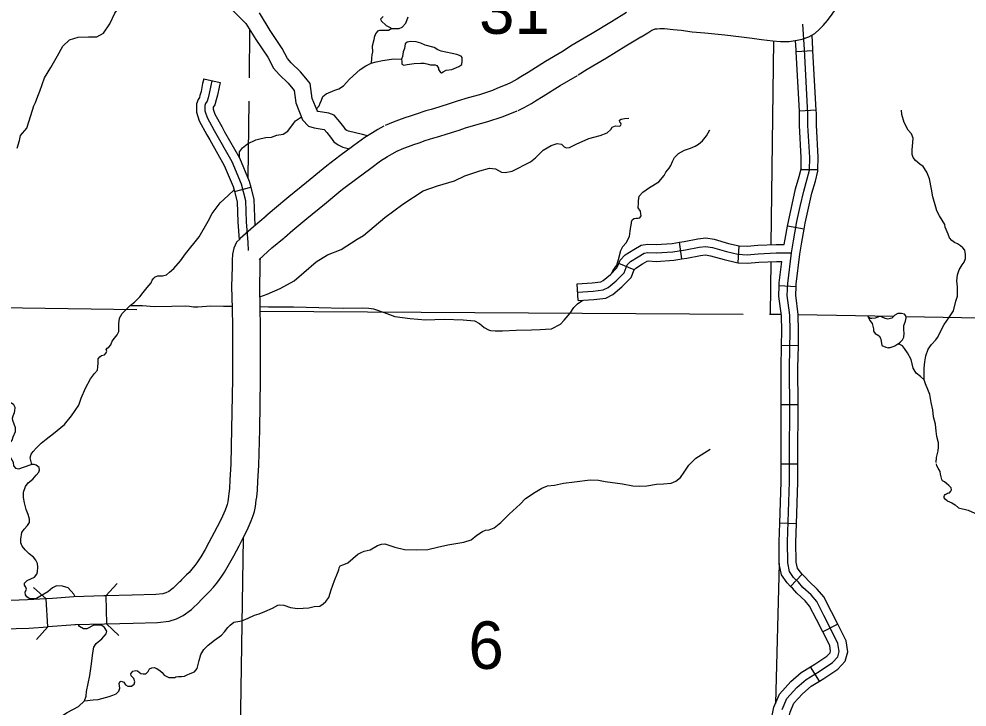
# Model space of a CAD drawing. Extents: x 813775 to 1157140, y 1757555 to 1979907.
# Drawn here: x 919245 to 936106, y 1805488 to 1817730 of the extents above; entities that cross this region are included whole.
import ezdxf

# ---------------------------------------------------------------- set-up
doc = ezdxf.new("R2010")
doc.units = 0
for name, color, linetype in [('Level 10', 7, 'Continuous'), ('Level 32', 7, 'Continuous'), ('Level 35', 7, 'Continuous'), ('Level 37', 7, 'Continuous'), ('Level 4', 7, 'Continuous'), ('Level 45', 7, 'Continuous'), ('Level 46', 7, 'Continuous'), ('Level 5', 7, 'Continuous')]:
    doc.layers.add(name, color=color, linetype=linetype)

msp = doc.modelspace()

# ---------------------------------------------------------------- linework, layer by layer
at = {"layer": 'Level 10'}
msp.add_line((919729, 1807412), (919728, 1807412), dxfattribs=at)
for points in [[(932941, 1817330), (933082, 1817351), (933176, 1817371), (933291, 1817410), (933399, 1817472), (933484, 1817548), (933549, 1817614), (933623, 1817700), (933708, 1817818), (933759, 1817895), (933804, 1817974), (933858, 1818084), (933893, 1818172), (933930, 1818273), (933950, 1818367), (933979, 1818481), (934011, 1818621), (934078, 1818907)], [(930052, 1817842), (929781, 1817681), (929436, 1817469), (929084, 1817263), (928913, 1817149)], [(932948, 1810031), (932952, 1810762), (932948, 1811526), (932961, 1812180), (932952, 1812461), (932908, 1812808), (932917, 1813026), (932984, 1813568), (933018, 1813784), (933081, 1814128), (933139, 1814395), (933201, 1814668), (933263, 1814886), (933303, 1815041), (933308, 1815268), (933277, 1815837), (933277, 1816041), (933214, 1817185), (933187, 1817639)], [(930309, 1817413), (930431, 1817486), (930500, 1817531), (930516, 1817539), (930559, 1817552), (930597, 1817557), (930641, 1817559), (930674, 1817559), (930726, 1817558), (930878, 1817542), (931020, 1817529), (931218, 1817503), (931444, 1817481), (931797, 1817447), (932093, 1817414), (932285, 1817389), (932451, 1817363), (932651, 1817339), (932786, 1817327), (932941, 1817330)], [(929190, 1816733), (929349, 1816839), (929693, 1817040), (930039, 1817253), (930307, 1817412)], [(928926, 1817158), (928608, 1816974), (928299, 1816778)], [(928301, 1816779), (928170, 1816698), (928106, 1816658), (928001, 1816601), (927907, 1816556)], [(928566, 1816355), (928867, 1816546), (929177, 1816725)], [(927921, 1816562), (927756, 1816496), (927664, 1816457), (927438, 1816382), (927234, 1816326), (927039, 1816270), (926914, 1816227), (926711, 1816162), (926574, 1816119), (926482, 1816095), (926310, 1816039), (926205, 1816003), (926105, 1815971), (925993, 1815929), (925900, 1815893), (925758, 1815833)], [(928121, 1816104), (928230, 1816155), (928358, 1816226), (928433, 1816273), (928565, 1816354)], [(925953, 1815373), (926087, 1815429), (926171, 1815461), (926270, 1815499), (926363, 1815529), (926468, 1815565), (926622, 1815614), (926714, 1815638), (926863, 1815686), (927071, 1815752), (927189, 1815793), (927369, 1815844), (927583, 1815903), (927840, 1815989), (927945, 1816033), (928107, 1816098)], [(925736, 1815822), (925626, 1815762), (925533, 1815704), (925397, 1815620), (925203, 1815477), (924953, 1815292), (924719, 1815118), (924654, 1815066), (924358, 1814823), (924043, 1814563), (923790, 1814350), (923638, 1814219)], [(923966, 1813841), (924114, 1813970), (924363, 1814179), (924676, 1814437), (924969, 1814677), (925025, 1814722), (925251, 1814891), (925501, 1815075), (925677, 1815205), (925798, 1815280), (925879, 1815331), (925975, 1815384)], [(923643, 1814223), (923413, 1814034), (923181, 1813822)], [(923178, 1813820), (923112, 1813757), (923068, 1813651), (923045, 1813547), (923037, 1813441), (923035, 1813322), (923027, 1812968), (923034, 1812576), (923041, 1812259), (923042, 1811776), (923040, 1811322), (923026, 1810437), (923011, 1809810), (922994, 1809530), (922987, 1809378), (922979, 1809290), (922971, 1809240), (922958, 1809138), (922948, 1809091), (922937, 1809054), (922912, 1808990), (922865, 1808884), (922827, 1808806), (922772, 1808694), (922718, 1808592), (922622, 1808413), (922558, 1808293), (922482, 1808159), (922443, 1808105), (922406, 1808052), (922370, 1808005), (922319, 1807944), (922269, 1807884), (922227, 1807842), (922135, 1807750), (922104, 1807718)], [(923518, 1813453), (923740, 1813656), (923961, 1813837)], [(922463, 1807370), (922491, 1807399), (922581, 1807489), (922638, 1807547), (922703, 1807623), (922762, 1807694), (922809, 1807757), (922850, 1807815), (922903, 1807889), (922996, 1808051), (923064, 1808178), (923159, 1808357), (923217, 1808465), (923277, 1808586), (923319, 1808674), (923374, 1808799), (923411, 1808894), (923432, 1808967), (923451, 1809054), (923465, 1809166), (923476, 1809224), (923486, 1809345), (923493, 1809504), (923511, 1809788), (923526, 1810427), (923540, 1811318), (923542, 1811776), (923540, 1812265), (923534, 1812586), (923527, 1812967), (923535, 1813313), (923536, 1813417), (923541, 1813472), (923542, 1813475)], [(932815, 1805442), (932899, 1805638), (933077, 1805833), (933246, 1805980), (933476, 1806123), (933712, 1806279), (933805, 1806381), (933832, 1806479), (933809, 1806621), (933721, 1806803), (933561, 1807114), (933432, 1807367), (933334, 1807483), (933188, 1807616), (933108, 1807710), (933019, 1807794), (932948, 1807901), (932917, 1808052), (932913, 1808425), (932948, 1809493), (932948, 1810031)], [(922108, 1807722), (921990, 1807605), (921910, 1807546), (921859, 1807522), (921804, 1807503), (921677, 1807489), (921261, 1807481), (920788, 1807466)], [(919728, 1807412), (919397, 1807393), (918947, 1807377), (918581, 1807360), (918462, 1807352), (918379, 1807350), (918272, 1807340), (918198, 1807326), (918090, 1807302), (917932, 1807258), (917819, 1807221), (917712, 1807173), (917572, 1807107), (917385, 1807018), (917163, 1806881), (916972, 1806779), (916557, 1806545), (916243, 1806375), (915913, 1806218), (915717, 1806116)], [(920220, 1807449), (919842, 1807419), (919728, 1807412)], [(919757, 1806913), (919729, 1807412)], [(920788, 1807466), (920754, 1807465), (920220, 1807449)], [(920788, 1807466), (920803, 1806966)], [(920803, 1806966), (921274, 1806981), (921710, 1806990), (921915, 1807013), (922047, 1807058), (922168, 1807115), (922316, 1807225), (922459, 1807366)], [(920803, 1806966), (920769, 1806965), (920241, 1806949)], [(915948, 1805672), (916136, 1805770), (916470, 1805929), (916799, 1806107), (917213, 1806340), (917413, 1806447), (917625, 1806578), (917786, 1806655), (917920, 1806718), (918000, 1806754), (918079, 1806780), (918212, 1806817), (918297, 1806836), (918340, 1806844), (918410, 1806850), (918487, 1806853), (918609, 1806861), (918967, 1806877), (919421, 1806893), (919757, 1806913)], [(920253, 1806950), (919757, 1806913)]]:
    msp.add_lwpolyline(points, dxfattribs=at)
at = {"layer": 'Level 32'}
for p, q in [((933366, 1817163), (933066, 1817147)), ((933423, 1816109), (933124, 1816092)), ((933453, 1815043), (933153, 1815048)), ((933209, 1813991), (932914, 1814045)), ((931033, 1813460), (930992, 1813757)), ((932037, 1813394), (932053, 1813693)), ((930188, 1813264), (929911, 1813380)), ((929189, 1812720), (929171, 1813020)), ((933065, 1812967), (932765, 1812979)), ((933106, 1811917), (932806, 1811923)), ((933102, 1810865), (932802, 1810863)), ((933098, 1809808), (932798, 1809808)), ((933073, 1808748), (932774, 1808758)), ((933175, 1807853), (932968, 1807635)), ((933808, 1806961), (933541, 1806824)), ((933481, 1805949), (933323, 1806204))]:
    msp.add_line(p, q, dxfattribs=at)
for points in [[(933366, 1817163), (933364, 1817193), (933349, 1817444)], [(933066, 1817147), (933065, 1817176), (933054, 1817347)], [(933124, 1816092), (933066, 1817147)], [(933423, 1816109), (933366, 1817163)], [(933153, 1815048), (933158, 1815265), (933127, 1815833), (933127, 1816037), (933124, 1816092)], [(933453, 1815043), (933458, 1815270), (933427, 1815841), (933427, 1816045), (933423, 1816109)], [(932914, 1814045), (932934, 1814157), (932993, 1814427), (933056, 1814705), (933118, 1814925), (933154, 1815062), (933153, 1815048)], [(933209, 1813991), (933228, 1814098), (933285, 1814362), (933346, 1814631), (933408, 1814846), (933453, 1815021), (933453, 1815043)], [(932856, 1813717), (932870, 1813810), (932914, 1814045)], [(933065, 1812967), (933067, 1813013), (933132, 1813547), (933166, 1813759), (933209, 1813991)], [(929911, 1813380), (929934, 1813436), (930024, 1813533), (930181, 1813629), (930310, 1813704), (930421, 1813726), (930576, 1813717), (930859, 1813738), (930992, 1813757)], [(930992, 1813757), (931072, 1813768), (931318, 1813817), (931459, 1813833), (931608, 1813811), (931863, 1813738), (932051, 1813693), (932053, 1813693)], [(932053, 1813693), (932195, 1813686), (932384, 1813703), (932710, 1813717), (932856, 1813717)], [(929180, 1812870), (929454, 1812887), (929636, 1812909), (929721, 1812953), (929867, 1813073), (930005, 1813215), (930063, 1813353), (930120, 1813415), (930258, 1813500), (930364, 1813562), (930431, 1813575), (930578, 1813567), (930875, 1813589), (931097, 1813620), (931341, 1813669), (931457, 1813682), (931577, 1813664), (931825, 1813593), (932029, 1813544), (932198, 1813535), (932393, 1813553), (932713, 1813567), (932984, 1813568)], [(929171, 1813020), (929441, 1813036), (929591, 1813054), (929637, 1813079), (929765, 1813184), (929877, 1813300), (929911, 1813380)], [(930188, 1813264), (930191, 1813271), (930216, 1813298), (930335, 1813371), (930418, 1813420), (930441, 1813425), (930579, 1813416), (930891, 1813440), (931033, 1813460)], [(931033, 1813460), (931122, 1813472), (931365, 1813520), (931454, 1813531), (931545, 1813517), (931787, 1813448), (932008, 1813395), (932037, 1813394)], [(932037, 1813394), (932201, 1813385), (932403, 1813404), (932717, 1813417), (932814, 1813417)], [(932765, 1812979), (932767, 1813038), (932814, 1813417)], [(929189, 1812720), (929468, 1812737), (929682, 1812763), (929804, 1812828), (929969, 1812963), (930132, 1813131), (930188, 1813264)], [(932806, 1811923), (932811, 1812179), (932803, 1812449), (932758, 1812801), (932765, 1812979)], [(933106, 1811917), (933111, 1812180), (933102, 1812473), (933058, 1812814), (933065, 1812967)], [(932802, 1810863), (932798, 1811527), (932806, 1811923)], [(933102, 1810865), (933098, 1811525), (933106, 1811917)], [(932798, 1809808), (932798, 1810031), (932802, 1810762), (932802, 1810863)], [(933098, 1809808), (933098, 1810030), (933102, 1810762), (933102, 1810865)], [(932774, 1808758), (932798, 1809496), (932798, 1809808)], [(933073, 1808748), (933098, 1809491), (933098, 1809808)], [(932968, 1807635), (932904, 1807697), (932807, 1807842), (932767, 1808036), (932763, 1808427), (932774, 1808758)], [(933175, 1807853), (933135, 1807891), (933089, 1807960), (933067, 1808068), (933063, 1808423), (933073, 1808748)], [(933808, 1806961), (933694, 1807182), (933558, 1807451), (933443, 1807587), (933296, 1807721), (933217, 1807813), (933175, 1807853)], [(933541, 1806824), (933427, 1807046), (933306, 1807284), (933226, 1807379), (933080, 1807512), (932999, 1807606), (932968, 1807635)], [(933323, 1806204), (933396, 1806249), (933613, 1806393), (933670, 1806455), (933678, 1806487), (933665, 1806575), (933586, 1806736), (933541, 1806824)], [(933481, 1805949), (933557, 1805997), (933810, 1806164), (933940, 1806306), (933985, 1806470), (933954, 1806666), (933855, 1806870), (933808, 1806961)], [(932633, 1805306), (932671, 1805488), (932771, 1805720), (932972, 1805941), (933156, 1806101), (933323, 1806204)], [(932926, 1805244), (932959, 1805397), (933027, 1805555), (933182, 1805726), (933335, 1805859), (933481, 1805949)]]:
    msp.add_lwpolyline(points, dxfattribs=at)
at = {"layer": 'Level 35'}
for points in [[(920630, 1817414), (920750, 1817480), (920861, 1817642), (920952, 1817834), (921053, 1817975), (921164, 1818278)], [(925722, 1817774), (925673, 1817728), (925693, 1817691)], [(925688, 1817694), (925773, 1817615), (925834, 1817583), (925876, 1817559), (925937, 1817561), (926006, 1817559), (926057, 1817583), (926123, 1817657), (926169, 1817769)], [(925876, 1817559), (925817, 1817522), (925734, 1817525), (925656, 1817525), (925619, 1817515), (925585, 1817464), (925563, 1817402), (925556, 1817358), (925526, 1817248), (925534, 1817148), (925519, 1817089), (925512, 1817033), (925508, 1816943)], [(919700, 1816680), (919813, 1816864), (919929, 1817074), (920025, 1817248), (920143, 1817356), (920300, 1817404), (920479, 1817409), (920630, 1817414)], [(926045, 1817016), (926051, 1816965), (926051, 1816924), (926090, 1816907), (926146, 1816919), (926271, 1816936), (926390, 1816943), (926449, 1816943), (926498, 1816934), (926562, 1816912), (926608, 1816912), (926647, 1816914), (926679, 1816902), (926706, 1816855), (926708, 1816833), (926728, 1816794), (926743, 1816775), (926760, 1816770), (926791, 1816789), (926843, 1816821), (926943, 1816828), (927065, 1816882), (927119, 1816921), (927129, 1816985), (927124, 1817044), (927109, 1817068), (927033, 1817098), (926752, 1817154), (926694, 1817181), (926630, 1817220), (926466, 1817264), (926390, 1817298), (926307, 1817323), (926207, 1817328), (926151, 1817318), (926112, 1817289), (926100, 1817205), (926078, 1817144), (926068, 1817063), (926045, 1817016)], [(924709, 1816400), (924865, 1816461), (924933, 1816488), (925019, 1816542), (925126, 1816657), (925315, 1816828), (925415, 1816897), (925508, 1816943), (925596, 1816968), (925711, 1816992), (925914, 1817019), (926045, 1817016)], [(919212, 1815429), (919254, 1815566), (919274, 1815657), (919387, 1815788), (919455, 1816011), (919511, 1816183), (919539, 1816246), (919581, 1816357), (919614, 1816448), (919700, 1816680)], [(924535, 1816129), (924584, 1816184), (924604, 1816231), (924626, 1816287), (924650, 1816348), (924709, 1816400)], [(935060, 1815754), (934985, 1815889), (934947, 1816033), (934940, 1816106)], [(923164, 1815259), (923168, 1815364), (923222, 1815438), (923310, 1815511), (923459, 1815580), (923550, 1815604), (923633, 1815619), (923736, 1815624), (923831, 1815661), (923944, 1815683), (924024, 1815736), (924127, 1815869), (924164, 1815920), (924269, 1815986)], [(925370, 1813878), (925749, 1814195), (926070, 1814434), (926436, 1814674), (926688, 1814760), (926991, 1814848), (927172, 1814938), (927443, 1815028), (927614, 1815075), (927722, 1815062), (927827, 1815004), (927890, 1815001), (928015, 1815021), (928340, 1815190), (928433, 1815258), (928568, 1815395), (928707, 1815481), (928817, 1815515), (928893, 1815503), (928939, 1815454), (928976, 1815437), (929035, 1815444), (929157, 1815500), (929377, 1815606), (929582, 1815659), (929704, 1815703), (929768, 1815766), (929797, 1815805), (929853, 1815827), (929929, 1815823), (929946, 1815842), (929956, 1815857), (929948, 1815874), (929929, 1815893), (929926, 1815928), (929953, 1815950), (930012, 1815957), (930090, 1815967)], [(931080, 1815395), (931187, 1815431), (931268, 1815465), (931329, 1815504), (931400, 1815560), (931471, 1815649), (931532, 1815759)], [(935549, 1814381), (935499, 1814563), (935474, 1814700), (935436, 1814884), (935388, 1815002), (935325, 1815103), (935267, 1815149), (935191, 1815212), (935149, 1815265), (935128, 1815318), (935131, 1815401), (935144, 1815532), (935146, 1815608), (935118, 1815686), (935060, 1815754)], [(930300, 1814310), (930258, 1814367), (930260, 1814453), (930260, 1814497), (930273, 1814575), (930339, 1814649), (930459, 1814730), (930627, 1814832), (930720, 1814943), (930747, 1815004), (930806, 1815077), (930835, 1815124), (930866, 1815191), (930904, 1815263), (930977, 1815337), (931080, 1815395)], [(922682, 1814270), (922826, 1814461), (922963, 1814590), (923070, 1814690)], [(922448, 1813853), (922609, 1814130), (922682, 1814270)], [(929781, 1813197), (929806, 1813246), (929875, 1813351), (929909, 1813451), (929946, 1813608), (929982, 1813679), (930043, 1813747), (930105, 1813860), (930114, 1813955), (930129, 1814039), (930136, 1814090), (930139, 1814119), (930158, 1814161), (930188, 1814180), (930219, 1814185), (930256, 1814185), (930285, 1814193), (930312, 1814227), (930307, 1814264), (930300, 1814310)], [(936066, 1813618), (936028, 1813659), (935988, 1813695), (935933, 1813730), (935882, 1813755), (935837, 1813791), (935794, 1813838), (935771, 1813899), (935718, 1814025), (935708, 1814076), (935617, 1814227), (935567, 1814315), (935549, 1814381)], [(923530, 1812786), (923656, 1812831), (923893, 1812936), (924142, 1813068), (924309, 1813222), (924529, 1813411), (924732, 1813531), (924976, 1813631), (925260, 1813812), (925370, 1813878)], [(922208, 1813552), (922448, 1813853)], [(921301, 1812694), (921396, 1812786), (921453, 1812862), (921526, 1812950), (921594, 1813038), (921616, 1813082), (921641, 1813119), (921670, 1813143), (921712, 1813160), (921761, 1813160), (921800, 1813160), (921871, 1813180), (921922, 1813224), (922000, 1813292), (922118, 1813429), (922208, 1813552)], [(935580, 1812062), (935698, 1812296), (935784, 1812414), (935862, 1812535), (935905, 1812709), (935935, 1812800), (935935, 1812962), (935927, 1813070), (935938, 1813176), (935965, 1813267), (936018, 1813355), (936053, 1813401), (936079, 1813471), (936079, 1813537), (936066, 1813618)], [(927142, 1812376), (927347, 1812361), (927433, 1812314), (927516, 1812241), (927594, 1812199), (927631, 1812190), (927716, 1812182), (927843, 1812180), (928085, 1812192), (928362, 1812199), (928513, 1812207), (928609, 1812209), (928714, 1812217), (928875, 1812300), (928939, 1812371), (929046, 1812498), (929115, 1812598), (929176, 1812664), (929273, 1812726)], [(921018, 1812167), (921022, 1812237), (921022, 1812305), (921035, 1812408), (921083, 1812491), (921164, 1812572), (921225, 1812631), (921301, 1812694)], [(921225, 1812631), (921444, 1812630), (921649, 1812613), (921965, 1812618), (922212, 1812625), (922280, 1812618), (922346, 1812611), (922424, 1812611), (922657, 1812628), (922882, 1812620), (923033, 1812623)], [(923533, 1812616), (923685, 1812606), (924130, 1812606), (924578, 1812596), (925020, 1812586), (925348, 1812591), (925465, 1812586), (925548, 1812571)], [(925548, 1812571), (925737, 1812508), (925930, 1812437), (926201, 1812402), (926472, 1812378), (926805, 1812388), (927142, 1812376)], [(934874, 1811944), (934917, 1811981), (934958, 1812024), (934983, 1812067), (934988, 1812133), (934983, 1812206), (934980, 1812277), (935013, 1812352), (935021, 1812415), (935018, 1812448), (934993, 1812478), (934942, 1812489), (934874, 1812489), (934824, 1812458), (934766, 1812408), (934698, 1812388), (934650, 1812398), (934584, 1812431), (934549, 1812436), (934501, 1812420), (934469, 1812405), (934411, 1812403), (934383, 1812403), (934340, 1812436), (934378, 1812365), (934416, 1812309), (934443, 1812219), (934443, 1812173), (934474, 1812133), (934542, 1812090), (934567, 1812052), (934577, 1811997), (934592, 1811923), (934660, 1811888), (934708, 1811881)], [(920351, 1810984), (920426, 1811161), (920515, 1811327), (920590, 1811420), (920644, 1811484), (920647, 1811543), (920654, 1811609), (920651, 1811662), (920656, 1811685), (920683, 1811719), (920715, 1811741), (920766, 1811753), (920798, 1811790), (920805, 1811822), (920798, 1811844), (920813, 1811873), (920842, 1811890), (920881, 1811932), (920903, 1811995), (920945, 1812052), (920989, 1812108), (921018, 1812167)], [(935409, 1811138), (935368, 1811240), (935346, 1811311), (935343, 1811386), (935343, 1811515), (935356, 1811631), (935373, 1811734), (935414, 1811853), (935472, 1811941), (935552, 1812020), (935580, 1812062)], [(935346, 1811311), (935280, 1811367), (935200, 1811430), (935149, 1811520), (935111, 1811672), (935048, 1811790), (934995, 1811866), (934958, 1811912), (934897, 1811944), (934874, 1811944), (934819, 1811906), (934733, 1811879), (934708, 1811881)], [(935556, 1809837), (935565, 1809930), (935593, 1810048), (935600, 1810109), (935600, 1810187), (935570, 1810303), (935555, 1810397), (935542, 1810523), (935512, 1810651), (935497, 1810773), (935469, 1810904), (935441, 1811048), (935409, 1811138)], [(919320, 1809749), (919237, 1809721), (919193, 1809734), (919154, 1809781), (919147, 1809838), (919103, 1809921), (919043, 1809988), (919022, 1810068), (919061, 1810156), (919126, 1810237), (919144, 1810294), (919183, 1810389), (919185, 1810457), (919136, 1810584), (919131, 1810625), (919141, 1810672), (919165, 1810726), (919170, 1810760), (919180, 1810819), (919152, 1810863), (919113, 1810897), (919012, 1810920), (918937, 1810941)], [(919472, 1809801), (919446, 1809919), (919461, 1809985), (919495, 1810034), (919549, 1810093), (919642, 1810181), (919730, 1810252), (919862, 1810357), (920052, 1810516), (920180, 1810671), (920312, 1810861), (920351, 1810984)], [(931077, 1809668), (931160, 1809791), (931281, 1809917), (931535, 1810076)], [(919293, 1808596), (919338, 1808652), (919395, 1808716), (919434, 1808773), (919434, 1808833), (919410, 1808916), (919374, 1809001), (919341, 1809120), (919328, 1809214), (919325, 1809309), (919361, 1809413), (919408, 1809480), (919493, 1809545), (919553, 1809612), (919599, 1809669), (919612, 1809708), (919602, 1809749), (919553, 1809791), (919514, 1809801), (919472, 1809801), (919320, 1809749)], [(929127, 1809495), (929404, 1809532), (929550, 1809527), (929671, 1809499), (929981, 1809459), (930162, 1809423), (930276, 1809416), (930409, 1809423), (930581, 1809451), (930707, 1809459), (930845, 1809469), (930926, 1809506), (931007, 1809570), (931077, 1809668)], [(935753, 1809155), (935717, 1809184), (935700, 1809208), (935699, 1809231), (935707, 1809250), (935719, 1809271), (935738, 1809284), (935757, 1809293), (935794, 1809300), (935816, 1809326), (935829, 1809353), (935821, 1809387), (935780, 1809430), (935742, 1809468), (935702, 1809493), (935671, 1809514), (935656, 1809536), (935654, 1809560), (935636, 1809632), (935625, 1809679), (935591, 1809739), (935571, 1809780), (935564, 1809816)], [(927155, 1808424), (927287, 1808465), (927390, 1808544), (927486, 1808609), (927542, 1808637), (927607, 1808642), (927693, 1808677), (927816, 1808773), (927960, 1808917), (928157, 1809096), (928255, 1809200), (928424, 1809313), (928542, 1809384), (928646, 1809422), (928769, 1809437), (928928, 1809470), (929127, 1809495)], [(935753, 1809155), (935836, 1809121), (935895, 1809083), (935952, 1809033), (936128, 1808989), (936245, 1808940), (936325, 1808896), (936405, 1808857), (936643, 1808741), (936798, 1808653), (936943, 1808635), (937033, 1808598), (937067, 1808560), (937121, 1808495), (937165, 1808448), (937165, 1808440), (937246, 1808339), (937310, 1808272), (937414, 1808218), (937577, 1808145), (937722, 1808052), (937847, 1807945)], [(920222, 1807495), (920121, 1807610), (920018, 1807641), (919914, 1807643), (919839, 1807610), (919759, 1807537), (919617, 1807454), (919555, 1807418), (919477, 1807416), (919428, 1807421), (919384, 1807449), (919361, 1807483), (919358, 1807532), (919376, 1807584), (919366, 1807618), (919345, 1807656), (919345, 1807690), (919392, 1807742), (919524, 1807801), (919562, 1807851), (919573, 1807895), (919578, 1807975), (919573, 1808040), (919542, 1808099), (919503, 1808156), (919428, 1808213), (919353, 1808288), (919304, 1808353), (919281, 1808407), (919278, 1808477), (919293, 1808596)], [(924753, 1807436), (924800, 1807572), (924856, 1807741), (924911, 1807867), (924934, 1807932), (924939, 1807965), (924959, 1807998), (925022, 1808023), (925093, 1808051), (925184, 1808129), (925274, 1808205), (925330, 1808235), (925385, 1808263), (925489, 1808288), (925620, 1808361), (925693, 1808384), (925753, 1808389), (925932, 1808333), (926101, 1808293), (926323, 1808283), (926514, 1808291), (926691, 1808333), (926872, 1808376), (927155, 1808424)], [(920242, 1807449), (920222, 1807495)], [(922292, 1806084), (922369, 1806115), (922415, 1806171), (922427, 1806221), (922452, 1806314), (922478, 1806423), (922533, 1806509), (922609, 1806587), (922722, 1806675), (922846, 1806764), (922899, 1806827), (922959, 1806902), (922999, 1806945), (923067, 1806996), (923209, 1807021), (923320, 1807071), (923433, 1807124), (923516, 1807147), (923617, 1807190), (923751, 1807248), (923846, 1807301), (923879, 1807306), (923957, 1807301)], [(923957, 1807301), (924072, 1807259), (924201, 1807244), (924400, 1807254), (924496, 1807274), (924594, 1807282), (924657, 1807322), (924705, 1807368), (924753, 1807436)], [(919835, 1805217), (920100, 1805392), (920305, 1805498), (920411, 1805596), (920439, 1805682), (920444, 1805767), (920504, 1806047), (920532, 1806257), (920561, 1806451), (920574, 1806555), (920615, 1806620), (920719, 1806703), (920794, 1806791), (920807, 1806840), (920768, 1806905), (920719, 1806936), (920636, 1806943), (920574, 1806943), (920452, 1806881), (920393, 1806879), (920323, 1806920), (920304, 1806951)], [(920411, 1805596), (920565, 1805615), (920651, 1805622), (920852, 1805675), (920913, 1805698), (920973, 1805726), (921021, 1805771), (921041, 1805824), (921034, 1805867), (921029, 1805907), (921039, 1805938), (921062, 1805948), (921112, 1805930), (921142, 1805882), (921183, 1805859), (921248, 1805859), (921293, 1805897), (921306, 1805938), (921286, 1805996), (921243, 1806041), (921235, 1806076), (921268, 1806129), (921321, 1806137), (921354, 1806132), (921414, 1806086), (921452, 1806076), (921503, 1806079), (921545, 1806119), (921568, 1806165), (921608, 1806187), (921649, 1806190), (921697, 1806175), (921755, 1806134), (921790, 1806102), (921825, 1806054), (921911, 1806013), (921964, 1806016), (922014, 1806016), (922032, 1806028), (922085, 1806031), (922135, 1806033), (922186, 1806038), (922234, 1806059), (922292, 1806084)]]:
    msp.add_lwpolyline(points, dxfattribs=at)
at = {"layer": 'Level 37'}
for points in [[(920788, 1807466), (920994, 1807684)], [(919505, 1807612), (919729, 1807412)], [(921021, 1806760), (920802, 1806966)], [(919756, 1806913), (919556, 1806689)]]:
    msp.add_lwpolyline(points, dxfattribs=at)
at = {"layer": 'Level 4'}
for points in [[(923344, 1817548), (923336, 1816683)], [(923331, 1816270), (923317, 1814900)], [(917669, 1812613), (921340, 1812559)], [(923535, 1812529), (932125, 1812479)], [(932590, 1812477), (932603, 1812476), (932799, 1812475)], [(933102, 1812471), (934803, 1812440)], [(935023, 1812436), (943214, 1812289), (943654, 1812281), (945498, 1812262)], [(923232, 1808495), (923134, 1802001), (923129, 1801720), (923070, 1798155)]]:
    msp.add_lwpolyline(points, dxfattribs=at)
at = {"layer": 'Level 45'}
for p, q in [((922531, 1816667), (922823, 1816597)), ((923077, 1814663), (923368, 1814737))]:
    msp.add_line(p, q, dxfattribs=at)
for points in [[(922531, 1816667), (922510, 1816580), (922483, 1816439), (922464, 1816366), (922454, 1816330), (922431, 1816295), (922400, 1816222), (922400, 1816074), (922452, 1815918), (922588, 1815670), (922640, 1815577)], [(922677, 1816632), (922657, 1816548), (922629, 1816406), (922609, 1816328), (922593, 1816267), (922563, 1816223), (922550, 1816192)], [(922823, 1816597), (922803, 1816516), (922776, 1816373), (922754, 1816290), (922731, 1816204), (922700, 1816158), (922700, 1816123), (922728, 1816039), (922850, 1815816), (922901, 1815724)], [(922550, 1816192), (922550, 1816098), (922590, 1815978), (922719, 1815743), (923029, 1815192), (923198, 1814796), (923274, 1814499), (923287, 1814121), (923314, 1813752), (923323, 1813612)], [(922640, 1815577), (922895, 1815125), (923056, 1814748), (923077, 1814663)], [(922901, 1815724), (923164, 1815258), (923341, 1814844), (923368, 1814737)], [(923368, 1814737), (923423, 1814520), (923439, 1814056)], [(923077, 1814663), (923124, 1814477), (923137, 1814113), (923160, 1813802)]]:
    msp.add_lwpolyline(points, dxfattribs=at)
at = {"layer": 'Level 46'}
for points in [[(922228, 1820087), (921931, 1820130), (921861, 1819642), (921885, 1819468), (921938, 1819363), (921995, 1819259), (922061, 1819198), (922095, 1819161), (922113, 1819140), (922125, 1819077), (922175, 1818939), (922262, 1818813), (922413, 1818645), (922586, 1818432), (922808, 1818137), (923282, 1817651)], [(924755, 1816056), (924564, 1816084), (924560, 1816085), (924547, 1816099), (924462, 1816314), (924423, 1816580), (924348, 1816676), (924253, 1816791), (924087, 1816947), (924019, 1817026), (923926, 1817205), (923710, 1817525), (923521, 1817836)], [(923282, 1817651), (923457, 1817363), (923668, 1817051), (923769, 1816857), (923870, 1816740), (924033, 1816585), (924115, 1816487), (924138, 1816458), (924170, 1816236), (924289, 1815936), (924392, 1815825), (924495, 1815791), (924672, 1815765)], [(925442, 1815648), (925353, 1815673), (925105, 1815732), (925078, 1815746), (925058, 1815760), (925022, 1815810), (924952, 1815899), (924850, 1816018), (924755, 1816056)], [(924672, 1815765), (924720, 1815709), (924783, 1815629), (924844, 1815545), (924922, 1815489), (925002, 1815449), (925125, 1815419)]]:
    msp.add_lwpolyline(points, dxfattribs=at)
at = {"layer": 'Level 5'}
for points in [[(932664, 1817338), (932619, 1813713)], [(932615, 1813412), (932603, 1812476)], [(932766, 1808043), (932698, 1805550)]]:
    msp.add_lwpolyline(points, dxfattribs=at)

# ---------------------------------------------------------------- texts
for s, height, p in [('31', 844.8, (927428, 1817465)), ('6', 845, (927238, 1806167))]:
    msp.add_text(s, height=height, dxfattribs=at).set_placement(p)

doc.saveas('drawing.dxf')
